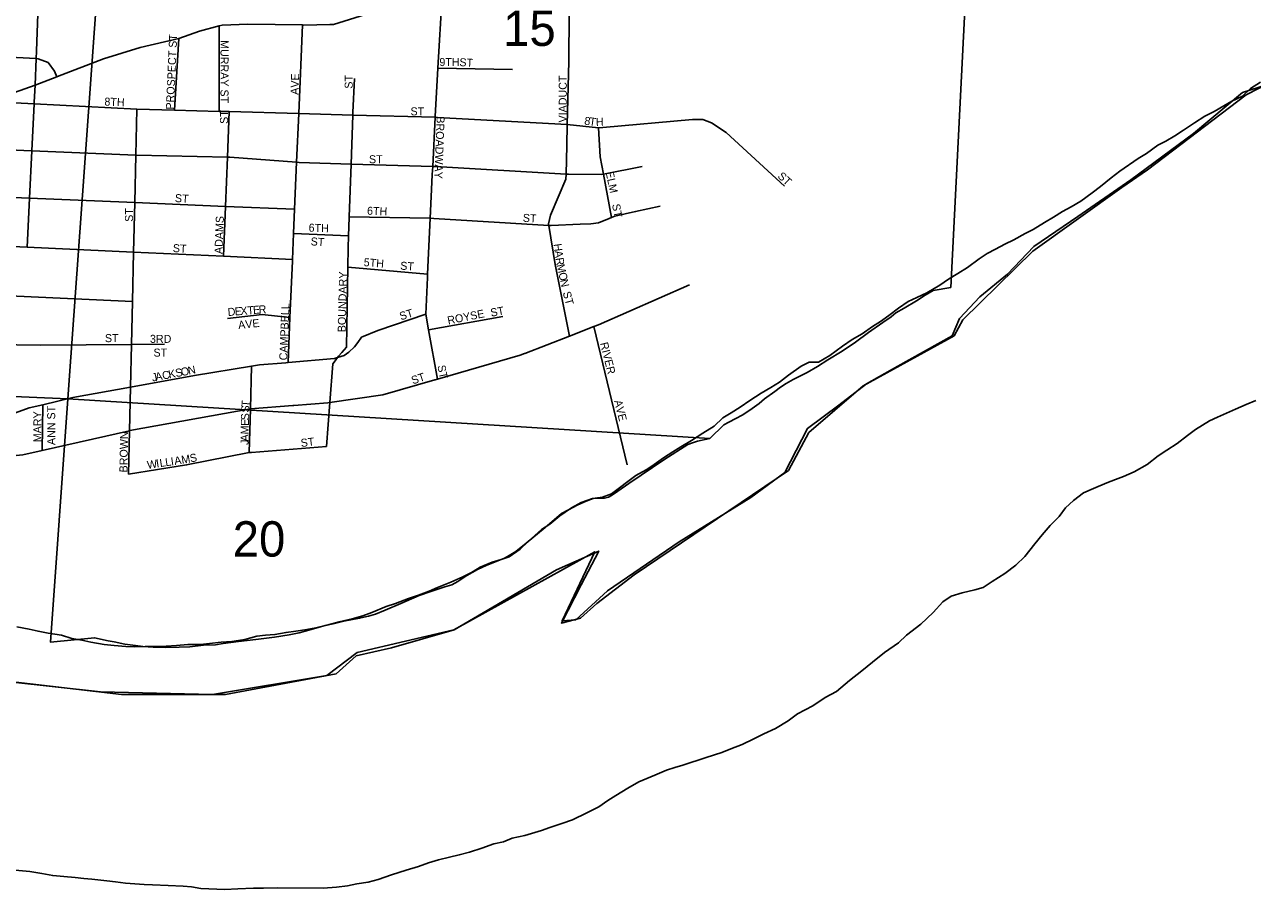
# Model space of a CAD drawing. Extents: x 1624196 to 2029251, y 146837 to 440034.
# Drawn here: x 1830604 to 1838276, y 263565 to 268968 of the extents above; entities that cross this region are included whole.
import ezdxf

# ---------------------------------------------------------------- set-up
doc = ezdxf.new("R2010")
doc.units = 0
for name, color, linetype in [('GM_X_City_Street', 7, 'Continuous'), ('GM_X_City_Street_Text', 7, 'Continuous'), ('GM_X_Corporation', 7, 'Continuous'), ('GM_X_County', 7, 'Continuous'), ('GM_X_Major_River', 7, 'Continuous'), ('GM_X_Section', 7, 'Continuous'), ('GM_X_Section_Text', 7, 'Continuous'), ('GM_X_Township', 7, 'Continuous')]:
    doc.layers.add(name, color=color, linetype=linetype)

msp = doc.modelspace()

# ---------------------------------------------------------------- linework, layer by layer
at = {"layer": 'GM_X_City_Street'}
for points in [[(1830678.3, 268803.1), (1830687.7, 269032.2), (1830693.5, 269175), (1830706.6, 269495.8), (1830706.7, 269496.4)], [(1833994.9, 268344), (1834004.1, 268737.2), (1834007.1, 269040), (1834035, 269254.8), (1834045.2, 269305.7), (1834073.4, 269386.8), (1834109.6, 269504.1)], [(1830380.8, 268488.5), (1830380.8, 268488.5), (1830669.5, 268589.1), (1830804.6, 268641.8), (1830808.9, 268643.5), (1831097.7, 268753.8), (1831326, 268824.4), (1831567.4, 268880.8), (1831697.1, 268927.9), (1831820.5, 268959.7), (1831837.8, 268964.1), (1831999.9, 268970.9), (1832340.7, 268965.6), (1832348, 268965.5), (1832510.9, 268967.6), (1832535.2, 268969.2), (1832801.1, 269051.8), (1833207.5, 269150), (1833213.5, 269152.5), (1833384.7, 269223.5), (1833526.1, 269258.9), (1833735.2, 269333.7)], [(1833151.9, 268030.4), (1833151.9, 268030.7), (1833154.3, 268081.3), (1833168.8, 268389.1), (1833169.1, 268394.2), (1833186.7, 268695.5), (1833213.5, 269152.5)], [(1826819.7, 268922.2), (1826821.6, 268922.1), (1826868.1, 268922.2), (1827473.2, 268923.4), (1827887, 268901.8), (1828226.1, 268884), (1828942.4, 268846.5), (1829345.4, 268825.4), (1829535.7, 268815.4), (1830022.6, 268789.9), (1830676.4, 268755.7), (1830688.8, 268755), (1830750.9, 268730.4), (1830790.6, 268677.7), (1830804.6, 268641.8)], [(1831820.8, 268544.4), (1831820.5, 268959.7)], [(1832277.5, 267489.3), (1832277.5, 267489.6), (1832278, 267500.4), (1832285, 267663.6), (1832291.4, 267814.3), (1832304, 268108.1), (1832317, 268412.3), (1832340.7, 268965.6)], [(1831541.4, 268433.4), (1831567.4, 268880.8)], [(1830664.4, 268483.2), (1830669.5, 268589.1), (1830676.4, 268755.7), (1830678.3, 268802.4), (1830678.3, 268803.1)], [(1833186.7, 268695.5), (1833652.1, 268687)], [(1832654.7, 268415.3), (1832654.9, 268419.1), (1832665, 268632)], [(1831820.8, 268425.8), (1831820.8, 268544.4), (1831820.8, 268544.4)], [(1830380.8, 268488.5), (1830663.9, 268473.6), (1831306.3, 268439.9), (1831541.4, 268433.4), (1831820.8, 268425.8), (1831883.3, 268424.1), (1832317, 268412.3), (1832654.3, 268403.1), (1833168.8, 268389.1), (1833184.9, 268388.6), (1833994.9, 268344)], [(1830620.1, 267576.9), (1830635.1, 267884.3), (1830649.5, 268178.7), (1830663.9, 268473.6), (1830664.4, 268482.5), (1830664.4, 268483.2)], [(1831252.6, 266160.1), (1831259, 266430.7), (1831265.5, 266702.5), (1831271.8, 266969.8), (1831278.1, 267238.7), (1831285.3, 267546.2), (1831292.6, 267856.5), (1831299.6, 268152.7), (1831306.3, 268439.9)], [(1831846.6, 267520.3), (1831859.3, 267832.5), (1831871.8, 268139.4), (1831883.3, 268424.1)], [(1832633, 267764.6), (1832633.1, 267766.8), (1832644.1, 268096.9), (1832654.3, 268403.1), (1832654.7, 268413.7), (1832654.7, 268415.3)], [(1834008.6, 267022.3), (1833919.7, 267469), (1833879.5, 267713.2), (1833878, 267722.6), (1833890.5, 267776.7), (1833987.1, 268002.8), (1833988, 268033.7), (1833993.2, 268211.7), (1833994.9, 268344)], [(1833994.9, 268344), (1834190.4, 268322.5), (1834218, 268324.9)], [(1834272.4, 267763.4), (1834221.8, 268033.5), (1834201.5, 268141.4), (1834190.4, 268322.5)], [(1834218, 268324.9), (1834778.4, 268375.1), (1834841.8, 268374.3), (1834896.5, 268355.3), (1834988.7, 268294.7), (1835353.2, 267957.8)], [(1829996.1, 268208.9), (1830645.1, 268178.9), (1830649.5, 268178.7), (1831299.6, 268152.7), (1831303.9, 268152.6), (1831871.8, 268139.4), (1831886.6, 268139.1), (1832304, 268108.1), (1832320.3, 268106.9), (1832644.1, 268096.9), (1833154.3, 268081.3), (1833172.1, 268080.8), (1833988, 268033.7), (1833989.4, 268033.6)], [(1833989.4, 268033.6), (1834003.5, 268032.8), (1834208.5, 268030.9), (1834221.8, 268033.5), (1834462.1, 268080.7)], [(1833121.7, 267389), (1833121.7, 267389.1), (1833122.7, 267408.7), (1833139.1, 267757.8), (1833151.9, 268030.4)], [(1829986.4, 267911.7), (1830635.1, 267884.3), (1831243.7, 267858.6)], [(1831243.7, 267858.6), (1831243.7, 267858.6), (1831292.6, 267856.5), (1831859.3, 267832.5), (1832291.4, 267814.3)], [(1832633.1, 267766.8), (1833139.1, 267757.8), (1833160.9, 267757.4), (1833879.5, 267713.2), (1833893.9, 267712.4), (1834074.8, 267720.7), (1834143.2, 267724.1), (1834189.5, 267729.7), (1834256.1, 267757.2), (1834272.4, 267763.4), (1834292.4, 267770.9), (1834421.2, 267799.8)], [(1834421.2, 267799.8), (1834421.4, 267799.8), (1834576.3, 267834.5)], [(1832544.7, 266867.8), (1832558.9, 266887.5), (1832565.9, 266897.1), (1832586.1, 266919), (1832614.6, 266952.9), (1832624.3, 267453.1), (1832626.6, 267573.6), (1832629.1, 267647.6), (1832632.9, 267763.3), (1832633, 267764.6)], [(1832285, 267663.6), (1832629.1, 267647.6)], [(1829976.3, 267606.6), (1830620.1, 267576.9), (1831285.3, 267546.2), (1831846.6, 267520.3), (1832278, 267500.4)], [(1832250.5, 266856.6), (1832262.5, 267139.1), (1832277.5, 267489.3)], [(1826870.9, 267428), (1827403, 267414.3), (1827956, 267389.3), (1828259.4, 267375.5), (1828855.5, 267348.5), (1829289.2, 267328.8), (1829625.8, 267313.6), (1829966.2, 267298.2), (1831278.1, 267238.7)], [(1832624.3, 267453.1), (1833122.7, 267408.7)], [(1833183.5, 266753.5), (1833128.5, 267061), (1833110.9, 267159.2), (1833121.7, 267389)], [(1833728.2, 266913), (1833730.8, 266914), (1834008.6, 267022.3), (1834160.9, 267081.7), (1834189.4, 267092.8), (1834758.4, 267342.6)], [(1831872.8, 267132.7), (1832088.1, 267156.7), (1832262.5, 267139.1)], [(1832552.9, 266885.6), (1832558.9, 266887.5), (1832600, 266900.8), (1832630.4, 266920.6), (1832664.8, 266954.5), (1832687.2, 266982.4), (1832709.7, 267014.3), (1832810.5, 267057.5), (1833110.9, 267159.2)], [(1833128.5, 267061), (1833593.1, 267144.6)], [(1834369.8, 266217.2), (1834160.9, 267081.7)], [(1831271.8, 266969.8), (1830706.5, 266964.8), (1829957.2, 266975.5)], [(1831271.8, 266969.8), (1831479.4, 266971.6)], [(1829938.4, 266554.3), (1830524.8, 266534.6), (1830633.6, 266573.7), (1830717.2, 266593.3), (1830905.5, 266637.5), (1831265.5, 266702.5), (1831666.4, 266775), (1832021.5, 266833.1), (1832073, 266841.5), (1832236.7, 266855.5)], [(1832236.7, 266855.5), (1832237.3, 266855.5), (1832250.5, 266856.6), (1832539.6, 266881.3), (1832552.9, 266885.6)], [(1832490, 266331.3), (1832511.9, 266606.4), (1832531.2, 266849.2), (1832543.8, 266866.6), (1832544.7, 266867.8)], [(1833167.1, 266748.8), (1833169.8, 266749.6), (1833183.5, 266753.5), (1833701.2, 266902.5), (1833728.2, 266913)], [(1832007.8, 266293.8), (1832014.7, 266566.8), (1832021.5, 266833.1)], [(1832280.8, 266587.5), (1832285.7, 266587.9), (1832498.7, 266604.4), (1832511.9, 266606.4), (1832842.8, 266655.4), (1833167.1, 266748.8)], [(1830185.6, 266262.2), (1830195.4, 266261.6), (1830323.1, 266253.2), (1830592.6, 266280.8), (1830713, 266307.9), (1831259, 266430.7), (1831261.2, 266431.2), (1832014.7, 266566.8), (1832280.8, 266587.5)], [(1830713, 266307.9), (1830717.2, 266593.3)], [(1832022.4, 266295), (1832490, 266331.3)], [(1831252.6, 266160.1), (1831616.8, 266216.9), (1832007.8, 266293.8), (1832022.4, 266295)]]:
    msp.add_lwpolyline(points, dxfattribs=at)
at = {"layer": 'GM_X_Corporation'}
msp.add_lwpolyline([(1838364.3, 268590.7), (1838215, 268543.5), (1837908.5, 268288.1), (1837515.5, 267997.3), (1837185.4, 267769.4), (1836910.3, 267580.7), (1836745.2, 267407.8), (1836572.3, 267266.3), (1836446.6, 267132.7), (1836399.4, 267022.7), (1836061.4, 266834.1), (1835864.9, 266724), (1835692, 266590.4), (1835495.5, 266445), (1835354, 266169.9), (1835141.8, 266012.7), (1834693.8, 265737.6), (1834245.8, 265431.1), (1834049.4, 265250.3), (1833962.9, 265242.5), (1834167.2, 265674.8), (1833286.9, 265187.5), (1832681.7, 265046), (1832493.1, 264900.6), (1831777.8, 264782.7), (1831078.3, 264798.5), (1830512.4, 264861.4)], dxfattribs=at)
at = {"layer": 'GM_X_County'}
msp.add_lwpolyline([(1838695.4, 268765.2), (1838237.5, 268528.4), (1837619.6, 268060.8), (1837459.6, 267950.4), (1836903.7, 267553), (1836465.8, 267123.6), (1836411.8, 267023.2), (1835843.9, 266712.2), (1835503.9, 266419.2), (1835377.9, 266182.4), (1834412.1, 265530.2), (1834180.1, 265351.6), (1834078.2, 265259.3), (1833958.2, 265229.2), (1834082.1, 265468), (1834192.1, 265678.7), (1833928.2, 265562.3), (1833288.3, 265187), (1832896.3, 265074.7), (1832676.4, 265024.5), (1832550.4, 264912.1), (1831860.5, 264783.7), (1831210.6, 264783.7), (1830030.7, 264920.2)], dxfattribs=at)
at = {"layer": 'GM_X_Major_River'}
for points in [[(1838326.3, 268608.6), (1838264, 268568.8), (1838213.8, 268520.9), (1838147.5, 268489.1), (1838097.4, 268461.3), (1838037.1, 268425.5), (1837979, 268395.8), (1837914.7, 268354), (1837846.4, 268308.2), (1837792.2, 268272.4), (1837736, 268240.6), (1837685.8, 268214.8), (1837613.5, 268163), (1837563.3, 268131.2), (1837446.9, 268051.6), (1837394.6, 268009.7), (1837326.3, 267955.9), (1837274.1, 267916.1), (1837203.8, 267864.3), (1837143.6, 267830.5), (1837089.4, 267800.7), (1837033.2, 267764.9), (1836977, 267731.1), (1836906.7, 267687.3), (1836856.5, 267663.5), (1836786.3, 267623.8), (1836730.1, 267596), (1836669.9, 267564.2), (1836619.7, 267538.5), (1836569.5, 267504.6), (1836495.2, 267450.8), (1836435, 267413), (1836376.8, 267377.2), (1836322.5, 267339.4), (1836242.2, 267291.7), (1836180, 267264), (1836125.9, 267238.2), (1836065.6, 267196.4), (1836003.3, 267150.6), (1835953.1, 267112.7), (1835902.9, 267082.9), (1835836.7, 267037.1), (1835774.4, 267001.3), (1835714.2, 266959.5), (1835635.9, 266899.8), (1835565.6, 266860), (1835507.5, 266858.4), (1835457.4, 266834.6), (1835377, 266776.8), (1835320.8, 266735), (1835266.6, 266701.2), (1835206.4, 266665.4), (1835136.1, 266619.6), (1835075.8, 266577.8), (1835019.6, 266542), (1834967.4, 266512.2), (1834913.1, 266458.3), (1834842.9, 266416.5), (1834770.6, 266368.8), (1834704.3, 266331)], [(1831350.8, 263596), (1831402.9, 263593.7), (1831500.9, 263589.1), (1831595, 263584.5), (1831647.1, 263580.2), (1831705.1, 263571.8), (1831755.2, 263569.5), (1831855.3, 263564.9), (1831937.4, 263568.4), (1832035.5, 263573.8), (1832097.6, 263573.5), (1832183.7, 263575), (1832470, 263573.2), (1832552.1, 263578.8), (1832622.3, 263588.4), (1832680.4, 263600.1), (1832750.5, 263609.7), (1832812.6, 263627.4), (1832896.9, 263657), (1832989.1, 263684.6), (1833065.3, 263708.2), (1833127.4, 263732), (1833189.6, 263749.7), (1833259.8, 263767.3), (1833319.9, 263781), (1833384, 263798.7), (1833460.2, 263822.3), (1833536.4, 263850), (1833596.5, 263861.7), (1833650.7, 263885.4), (1833728.9, 263901), (1833833.1, 263932.5), (1833885.3, 263952.3), (1833961.5, 263976), (1834027.6, 263999.6), (1834117.9, 264043.3), (1834192.2, 264081), (1834248.4, 264120.8), (1834298.6, 264152.6), (1834372.9, 264198.4), (1834443.1, 264238.1), (1834541.4, 264279.7), (1834615.6, 264309.4), (1834667.8, 264327.1), (1834717.9, 264340.9), (1834862.3, 264388.2), (1834960.5, 264419.8), (1835016.7, 264443.5), (1835086.9, 264471.2), (1835161.1, 264504.9), (1835223.3, 264536.7), (1835295.5, 264570.4), (1835375.8, 264618.1), (1835434.1, 264661.9), (1835530.4, 264711.5), (1835606.7, 264763.3), (1835677, 264801), (1835759.4, 264870.8), (1835835.7, 264930.6), (1835902, 264984.4), (1835978.3, 265044.2), (1836064.7, 265105.9), (1836115, 265153.8), (1836203.4, 265221.6), (1836281.8, 265295.4), (1836342.1, 265361.3), (1836394.3, 265397.1), (1836462.5, 265418.8), (1836540.7, 265436.4), (1836592.8, 265452.2), (1836651, 265488), (1836729.3, 265537.7), (1836797.6, 265591.5), (1836853.9, 265645.4), (1836916.3, 265723.3), (1836962.6, 265781.3), (1837012.9, 265839.2), (1837069.2, 265895.1), (1837107.5, 265949.1), (1837157.8, 265995), (1837220, 266042.8), (1837282.2, 266070.5), (1837366.5, 266106.2), (1837420.6, 266125.9), (1837470.8, 266145.7), (1837537, 266173.4), (1837619.3, 266219.1), (1837687.6, 266272.9), (1837741.8, 266308.8), (1837806, 266350.5), (1837870.3, 266400.3), (1837920.5, 266438.2), (1838008.9, 266491.9), (1838059, 266515.7), (1838113.2, 266539.5), (1838171.4, 266565.2), (1838237.6, 266594.9), (1838297.8, 266618.7)], [(1834704.3, 266331), (1834654.2, 266299.2), (1834595.9, 266261.4), (1834537.7, 266219.6), (1834487.5, 266185.8), (1834423.3, 266152), (1834270.6, 266036.4), (1834214.4, 266014.7), (1834152.3, 266007), (1834082.1, 265983.3), (1834021.9, 265949.6), (1833947.6, 265899.8), (1833885.3, 265846), (1833833.1, 265814.2), (1833750.7, 265738.3), (1833700.5, 265690.5), (1833632.2, 265642.7), (1833582, 265626.9), (1833525.9, 265609.2), (1833451.7, 265577.5), (1833397.5, 265545.7), (1833343.3, 265517.9), (1833267.1, 265484.2), (1833184.8, 265450.6), (1833132.7, 265428.8), (1833064.5, 265403.1), (1833002.3, 265383.4), (1832922.1, 265351.7), (1832864, 265332), (1832773.7, 265294.4), (1832717.5, 265274.7), (1832651.4, 265255), (1832569.2, 265237.4), (1832493, 265215.8), (1832424.9, 265200.1), (1832354.7, 265186.5), (1832298.6, 265178.8), (1832238.5, 265171.1), (1832168.4, 265157.5), (1832110.3, 265153.8), (1832056.2, 265148.1), (1831980.1, 265126.5), (1831899.9, 265114.9), (1831831.8, 265109.3), (1831759.7, 265101.7), (1831703.6, 265096), (1831623.5, 265094.5), (1831553.4, 265088.9), (1831489.3, 265085.2), (1831409.2, 265081.7), (1831357.1, 265082), (1831293.1, 265080.4), (1831237, 265082.7), (1831164.9, 265089.2), (1831100.9, 265095.6), (1831018.9, 265110.2), (1830960.9, 265122.5), (1830898.8, 265133), (1830834.8, 265153.4), (1830750.8, 265166), (1830688.8, 265178.4), (1830632.8, 265190.8), (1830554.7, 265205.3)], [(1830500.2, 263689.5), (1830636.3, 263676.6), (1830712.4, 263664.1), (1830780.4, 263651.7), (1830848.4, 263645.2), (1830920.5, 263638.8), (1830974.5, 263632.4), (1831024.6, 263628.1), (1831118.6, 263619.5), (1831172.7, 263613.2), (1831234.7, 263604.8), (1831350.8, 263596)]]:
    msp.add_lwpolyline(points, dxfattribs=at)
at = {"layer": 'GM_X_Section'}
for points in [[(1825700.4, 271896.6), (1831225.6, 271518.8), (1830874.1, 266630.3), (1825603.3, 266857), (1825739.5, 269482.3)], [(1830874.1, 266630.3), (1834885.1, 266383), (1834809.1, 266365.4), (1834777, 266355.5), (1834748.9, 266343.7), (1834604.5, 266252.4), (1834379.8, 266101.4), (1834311.5, 266053.7), (1834271.4, 266025.9), (1834253.3, 266016), (1834227.3, 266010.1), (1834191.3, 266010.3), (1834157.3, 266006.5), (1834113.2, 265990.7), (1834057.1, 265965), (1834002.9, 265937.2), (1833958.8, 265913.4), (1833930.7, 265887.6), (1833856.4, 265825.9), (1833737.9, 265728.5), (1833673.7, 265676.8), (1833631.6, 265651), (1833603.5, 265635.1), (1833571.4, 265621.3), (1833493.3, 265591.6), (1833433.1, 265563.9), (1833367, 265526.3), (1833310.8, 265488.5), (1833274.7, 265468.7), (1833230.6, 265454.9), (1833142.4, 265425.3), (1833070.3, 265401.6), (1832956.1, 265352.2), (1832857.9, 265308.7), (1832797.8, 265285), (1832753.7, 265271.2), (1832697.6, 265259.4), (1832599.5, 265239.9), (1832531.5, 265224.2), (1832481.4, 265214.5), (1832379.2, 265184.9), (1832319.2, 265167.2), (1832257.1, 265155.6), (1832165, 265142), (1832049, 265126.5), (1831940.9, 265113.1), (1831844.8, 265101.5), (1831796.8, 265093.7), (1831722.8, 265090.1), (1831636.7, 265080.5), (1831570.7, 265078.8), (1831486.7, 265077.2), (1831406.7, 265077.6), (1831342.7, 265081.9), (1831296.8, 265088.1), (1831230.8, 265096.4), (1831162.9, 265112.8), (1831126.9, 265119), (1831041, 265137.4), (1830766.8, 265108.7)]]:
    msp.add_lwpolyline(points, close=True, dxfattribs=at)
msp.add_lwpolyline([(1836592.9, 271331.1), (1836391.7, 267325.8), (1836281.6, 267306.4), (1836231.5, 267276.6), (1836177.3, 267242.9), (1836101.1, 267197.2), (1836048.9, 267167.5), (1836018.8, 267141.6), (1835966.7, 267105.9), (1835878.3, 267044.3), (1835796.1, 266984.7), (1835711.8, 266927.1), (1835623.5, 266873.5), (1835559.3, 266831.8), (1835493.1, 266794.1), (1835406.9, 266750.5), (1835362.8, 266726.8), (1835326.7, 266702.9), (1835292.5, 266675.1), (1835228.3, 266629.4), (1835194.2, 266601.5), (1835136, 266559.8), (1835087.8, 266528), (1835047.7, 266506.3), (1835005.6, 266484.4), (1834973.5, 266466.6), (1834885.1, 266383), (1830874.1, 266630.3), (1831225.6, 271518.8)], dxfattribs=at)
at = {"layer": 'GM_X_Township'}
msp.add_lwpolyline([(1838695.4, 268765.2), (1838237.5, 268528.4), (1837619.6, 268060.8), (1837459.6, 267950.4), (1836903.7, 267553), (1836465.8, 267123.6), (1836411.8, 267023.2), (1835843.9, 266712.2), (1835503.9, 266419.2), (1835377.9, 266182.4), (1834412.1, 265530.2), (1834180.1, 265351.6), (1834078.2, 265259.3), (1833958.2, 265229.2), (1834082.1, 265468), (1834192.1, 265678.7), (1833928.2, 265562.3), (1833288.3, 265187), (1832896.3, 265074.7), (1832676.4, 265024.5), (1832550.4, 264912.1), (1831860.5, 264783.7), (1831210.6, 264783.7), (1830030.7, 264920.2)], dxfattribs=at)

# ---------------------------------------------------------------- texts
at = {"layer": 'GM_X_City_Street_Text'}
for s, rotation, p in [('PROSPECT ST', 87.39642, (1831536.6, 268436.1)), ('MURRAY ST', 270, (1831828.3, 268871.2)), ('9TH', 0.00001, (1833196, 268709)), ('ST', 356.42537, (1833319.8, 268709)), ('AVE', 88.0187, (1832315.4, 268528.4)), ('ST', 90, (1832654.2, 268567.6)), ('VIADUCT', 90, (1833991.8, 268356.4)), ('8TH', 357.71079, (1831102, 268462.6)), ('ST', 90, (1831875.4, 268347.6)), ('ST', 0.00001, (1833015.6, 268401)), ('BROADWAY', 267.88009, (1833179, 268395.7)), ('8', 352.18562, (1834099.4, 268343.7)), ('T', 352.17701, (1834130, 268339.6)), ('H', 2.5455, (1834174.7, 268334.3)), ('ST', 0.00001, (1832756, 268101.8)), ('ELM', 281.68987, (1834234.8, 268045.9)), ('ST', 317.49286, (1835305.6, 268015.8)), ('ST', 356.42537, (1831542.2, 267859.8)), ('ST', 280.61472, (1834274.5, 267843.4)), ('ST', 90, (1831281.4, 267736)), ('ADAMS', 87.71069, (1831840.2, 267534)), ('6TH', 357.70642, (1832743.2, 267780.6)), ('ST', 356.42537, (1833715.8, 267736.6)), ('6TH', 357.70642, (1832378, 267675)), ('ST', 356.41856, (1832390.5, 267589.2)), ('ST', 356.42622, (1831529, 267547.4)), ('H', 277.91529, (1833909.3, 267596.5)), ('A', 277.91529, (1833915.4, 267552.9)), ('5TH', 355.42452, (1832721.6, 267459.4)), ('ST', 356.42537, (1832950.2, 267437.4)), ('R', 278.73476, (1833921.6, 267508.6)), ('M', 282.28596, (1833928.2, 267466.1)), ('BOUNDARY', 88.55058, (1832610.2, 267045.5)), ('O', 282.88861, (1833939.5, 267413.9)), ('N', 282.87257, (1833949.4, 267371.1)), ('ST', 284.92417, (1833966.3, 267294.1)), ('D', 4.63841, (1831875.2, 267147)), ('E', 4.63811, (1831919.1, 267150.5)), ('X', 4.63789, (1831954.2, 267153.4)), ('T', 4.63811, (1831998, 267157)), ('E', 4.63169, (1832033.1, 267159.8)), ('R', 2.59925, (1832067.7, 267162.6)), ('CAMPBELL', 87.67677, (1832245, 266869.6)), ('ST', 17.3548, (1832955.6, 267120.2)), ('ROYSE', 11.309, (1833251.4, 267094.1)), ('ST', 10.6213, (1833519.9, 267142.5)), ('AVE', 5.90678, (1831941.1, 267065.8)), ('ST', 0.00001, (1831106, 266984.2)), ('3RD', 0.00001, (1831387.6, 266979.8)), ('ST', 0.00001, (1831409.6, 266893.8)), ('RIVER', 284.03368, (1834199.6, 266977.1)), ('J', 10.61965, (1831403.5, 266737.7)), ('A', 10.62621, (1831425.2, 266741.7)), ('C', 10.63017, (1831468.4, 266749.8)), ('K', 10.62621, (1831507.3, 266757.1)), ('S', 10.62468, (1831550.6, 266765.3)), ('O', 10.62621, (1831585.1, 266771.8)), ('N', 12.33571, (1831630, 266780.2)), ('ST', 18.43932, (1833030.3, 266719.8)), ('ST', 281.31834, (1833183.3, 266835.9)), ('T', 85.54262, (1832008.6, 266578.2)), ('AVE', 284.03625, (1834287.6, 266616.3)), ('MARY', 90, (1830709.4, 266358.8)), ('ANN ST', 90, (1830795.5, 266341.2)), ('S', 87.37634, (1832007.1, 266543.5)), ('E', 88.88282, (1832005.4, 266460.2)), ('S', 88.85232, (1832006.1, 266495.4)), ('BROWN', 88.89469, (1831246.2, 266169.8)), ('A', 88.84155, (1832003.5, 266363.4)), ('M', 88.86293, (1832004.3, 266407.4)), ('ST', 7.12165, (1832332.5, 266328.6)), ('J', 88.8634, (1832003, 266341.4)), ('W', 8.29298, (1831373.1, 266192.1)), ('I', 8.28146, (1831429.7, 266200.4)), ('L', 8.29482, (1831451.4, 266203.6)), ('L', 8.28081, (1831486.3, 266208.6)), ('I', 8.30407, (1831521.1, 266213.7)), ('A', 8.29084, (1831542.9, 266216.9)), ('M', 9.71194, (1831587.8, 266223.5)), ('S', 11.26188, (1831641.3, 266232.6))]:
    msp.add_text(s, height=50, rotation=rotation, dxfattribs=at).set_placement(p)
at = {"layer": 'GM_X_Section_Text'}
for s, p in [('15', (1833594.2, 268834.7)), ('20', (1831904.6, 265644.2))]:
    msp.add_text(s, height=221, rotation=0.00001, dxfattribs=at).set_placement(p)

doc.saveas('drawing.dxf')
